// Mitsubishi GX Works2 project: MC-30MR-4MTS-F700-FX-8C   PLC: FX1S

PROGRAM MAIN
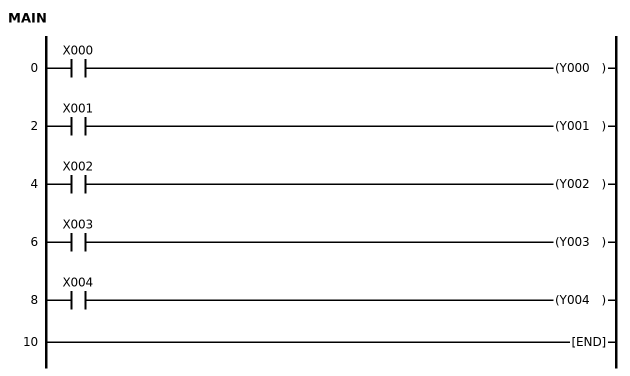
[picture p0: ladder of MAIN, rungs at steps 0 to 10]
0     LD      X000
      OUT     Y000
2     LD      X001
      OUT     Y001
4     LD      X002
      OUT     Y002
6     LD      X003
      OUT     Y003
8     LD      X004
      OUT     Y004
10    END
END_PROGRAM
